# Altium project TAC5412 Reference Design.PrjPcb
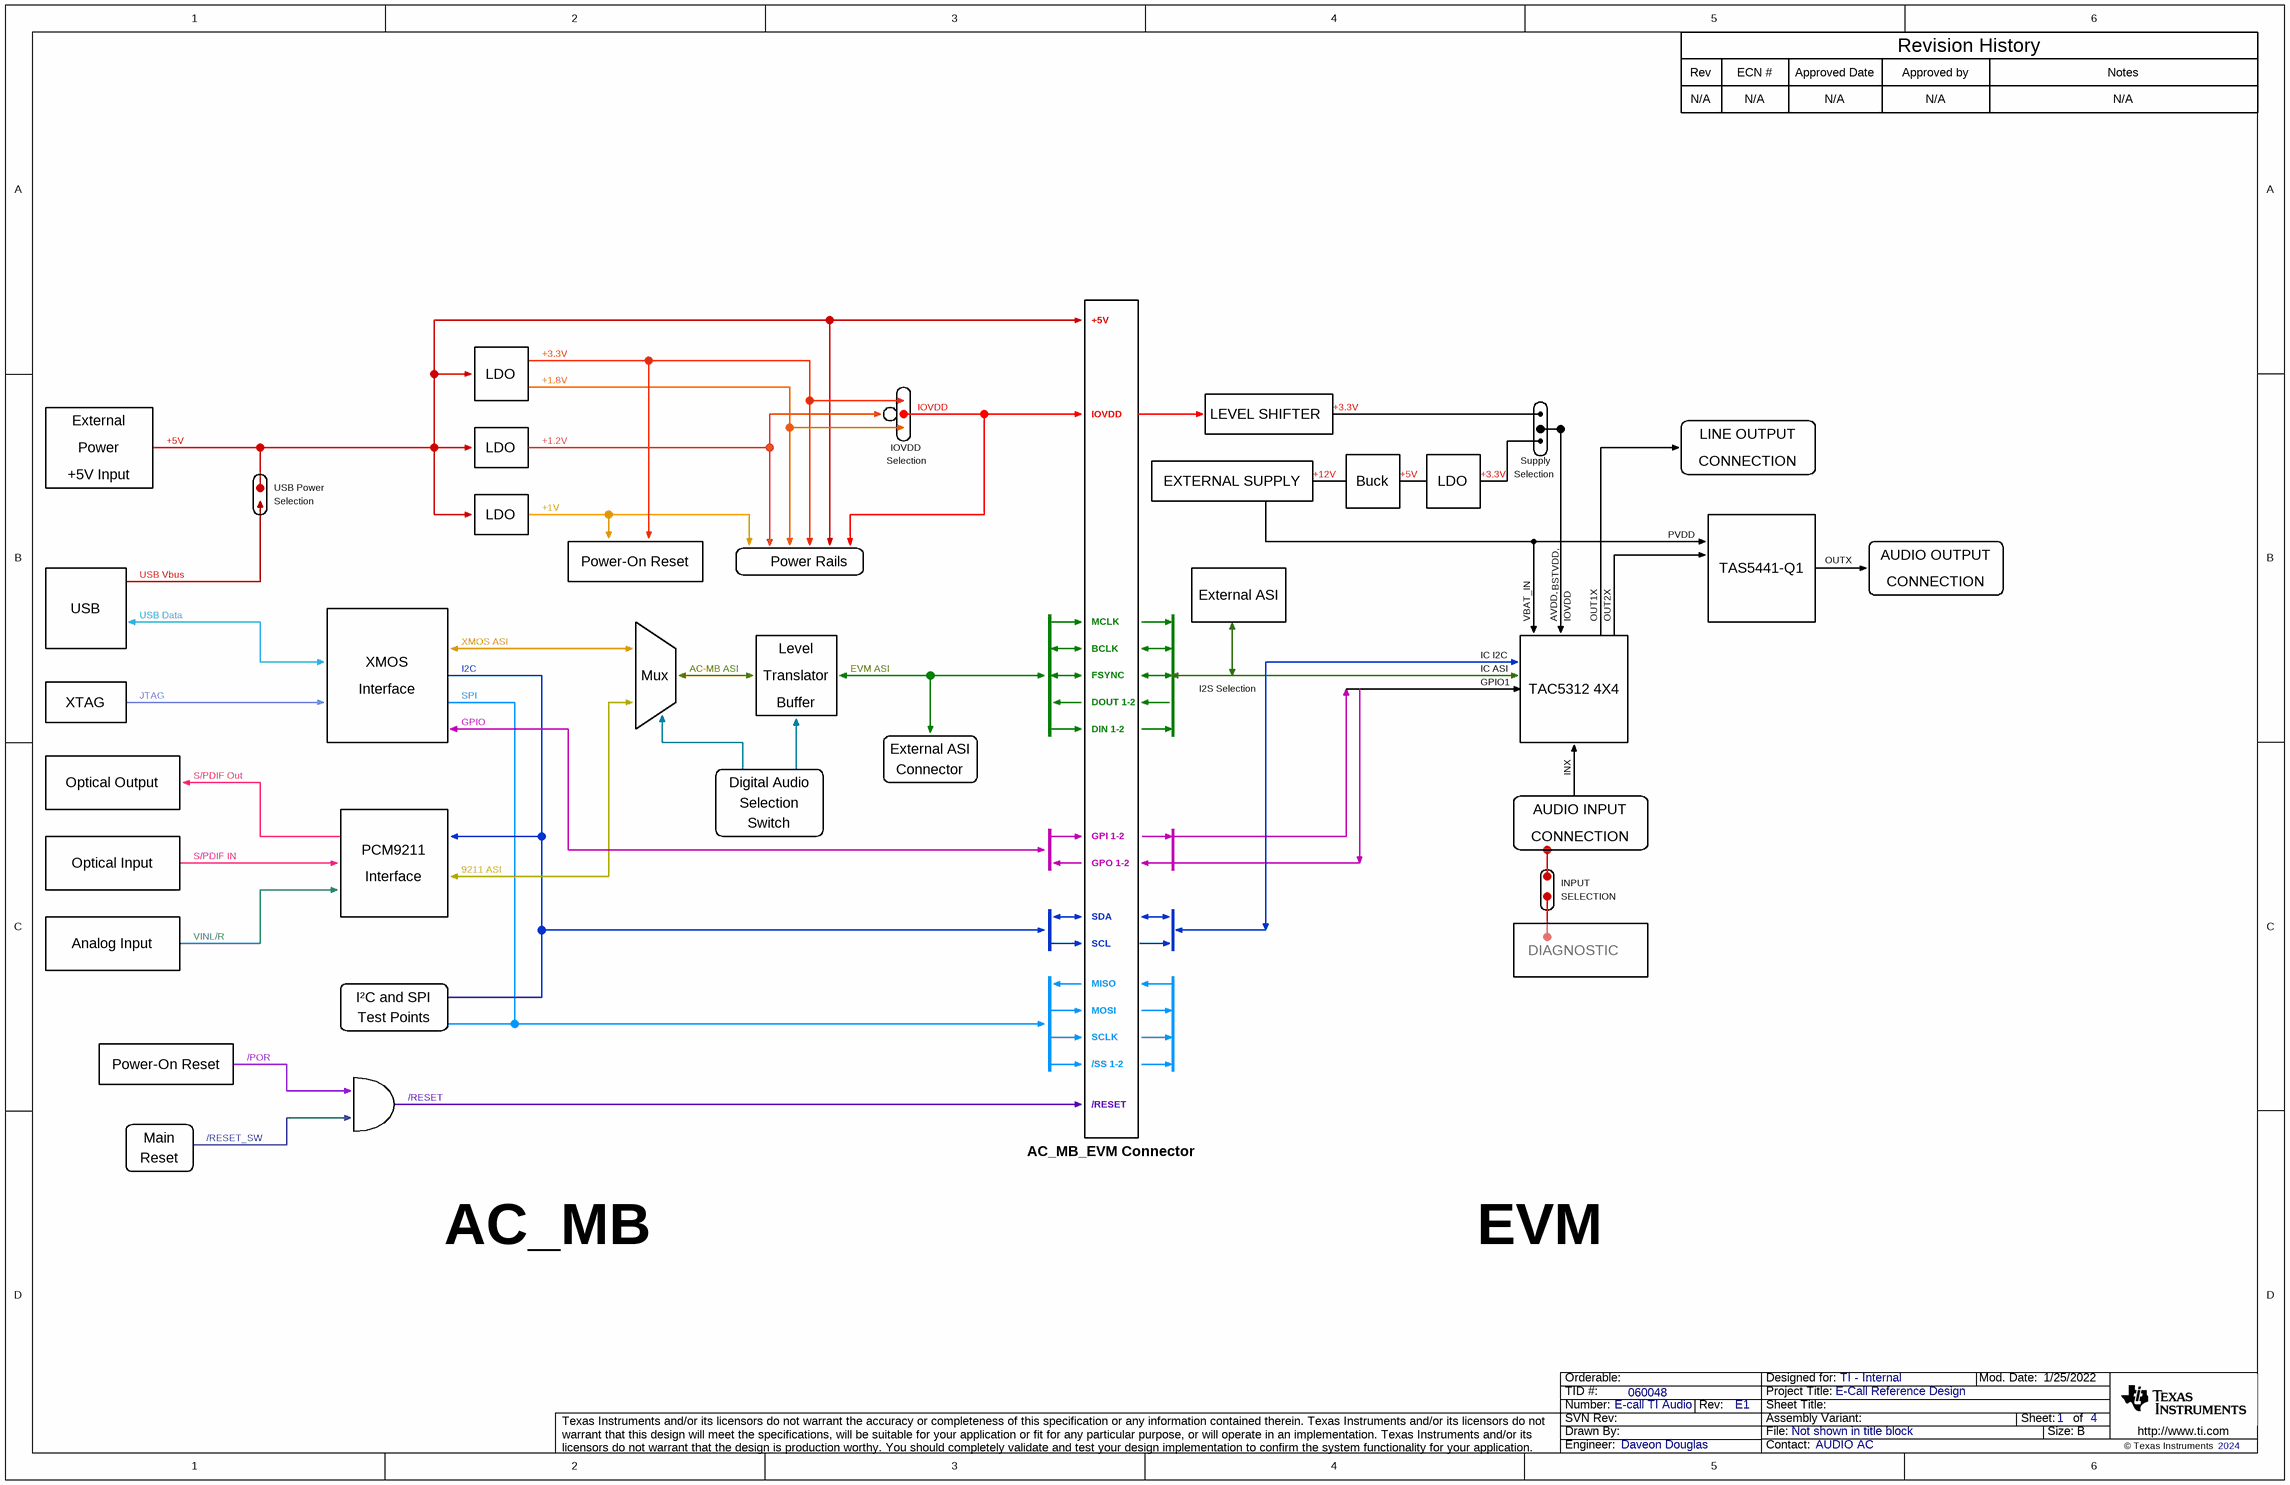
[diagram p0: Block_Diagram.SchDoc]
CopyrightYear: 2024; PCB_Layout: Daveon Douglas; PCB_Rev: Rev A; PRJ_Customer: TI - Internal; PRJ_Engineer: Daveon Douglas; PRJ_Number: E-call TI Audio; PRJ_Title: E-Call Reference Design; SCH_Rev: E1; TechSupport: AUDIO AC; TID: 060048
4 sheets, 139 parts. Net scope: flat (ports and power ports of the same name join across sheets).
Board file: TAC5412 Reference Design.PcbDoc
Sheets:
  Block_Diagram.SchDoc
  Schematic1.SchDoc
  Schematic2.SchDoc
  Hardware.SchDoc

## Sheet Block_Diagram.SchDoc
size 431 x 279 mm; Date: Not shown in title block; ApprovedBy: Not shown in title block; CheckedBy: Not shown in title block; Author: Not shown in title block; CompanyName: Not shown in title block; Engineer: Not shown in title block; Organization: Not shown in title block; Address1: Not shown in title block; Address2: Not shown in title block; Address3: Not shown in title block; Address4: Not shown in title block; DocumentNumber: 1; Revision: Use project parameter SCH_Rev; SheetNumber: 1; SheetTotal: 4; PageSetup: Record=PageOptions¦CenterHorizontal=True¦CenterVertical=True¦PrintScale=1.00¦XCorrection=1.00¦YCorrection=1.00¦PrintKind=0¦BorderSize=5000000¦LeftOffset=0¦BottomOffset=0¦Orientation=2¦PaperLength=1000¦PaperWidth=1000¦Scale=100¦PaperSource=15¦PrintQuality=600¦MediaType=1¦DitherType=10¦PaperKind=Letter¦PrintScaleMode=1

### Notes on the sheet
- Rev
- N/A
- ECN #
- Approved Date
- Approved by
- Revision History
- Notes
- +3.3V
- +5V
- External
- LDO
- +1.8V
- IOVDD
- LEVEL SHIFTER
- LINE OUTPUT
- +5V Input
- Power
- USB Power
- Selection
- +1.2V
- EXTERNAL SUPPLY
- +12V
- Buck
- Supply
- CONNECTION
- +1V
- Power-On Reset
- Power Rails
- PVDD
- TAS5441-Q1
- OUTX
- AUDIO OUTPUT
- USB
- USB Data
- USB Vbus
- MCLK
- External ASI
- VBAT_IN
- BSTVDD,
- AVDD,
- OUT1X
- OUT2X
- XTAG
- JTAG
- XMOS
- Interface
- SPI
- I2C
- XMOS ASI
- Mux
- AC-MB ASI
- Buffer
- Level
- Translator
- EVM ASI
- BCLK
- FSYNC
- DOUT 1-2
- I2S Selection
- IC ASI
- IC I2C
- GPIO1
- TAC5312 4X4
- GPIO
- Connector
- DIN 1-2
- Optical Output
- S/PDIF Out
- Digital Audio
- Switch
- GPI 1-2
- INX
- AUDIO INPUT
- Optical Input
- S/PDIF IN
- PCM9211
- 9211 ASI
- GPO 1-2
- INPUT
- SELECTION
- Analog Input
- VINL/R
- SDA
- SCL
- DIAGNOSTIC
- I²C and SPI
- Test Points
- MISO
- MOSI
- SCLK
- /POR
- /RESET
- /SS 1-2
- Main
- Reset
- /RESET_SW
- AC_MB_EVM Connector
- AC_MB
- EVM

## Sheet Schematic1.SchDoc
size 431 x 279 mm; Date: Not shown in title block; ApprovedBy: Not shown in title block; CheckedBy: Not shown in title block; Author: Not shown in title block; CompanyName: Not shown in title block; Engineer: Not shown in title block; Organization: Not shown in title block; Address1: Not shown in title block; Address2: Not shown in title block; Address3: Not shown in title block; Address4: Not shown in title block; DocumentNumber: 2; Revision: Use project parameter SCH_Rev; SheetNumber: 2; SheetTotal: 4; PageSetup: Record=PageOptions¦CenterHorizontal=True¦CenterVertical=True¦PrintScale=1.00¦XCorrection=1.00¦YCorrection=1.00¦PrintKind=0¦BorderSize=5000000¦LeftOffset=0¦BottomOffset=0¦Orientation=2¦PaperLength=1000¦PaperWidth=1000¦Scale=100¦PaperSource=15¦PrintQuality=600¦MediaType=1¦DitherType=10¦PaperKind=Letter¦PrintScaleMode=1
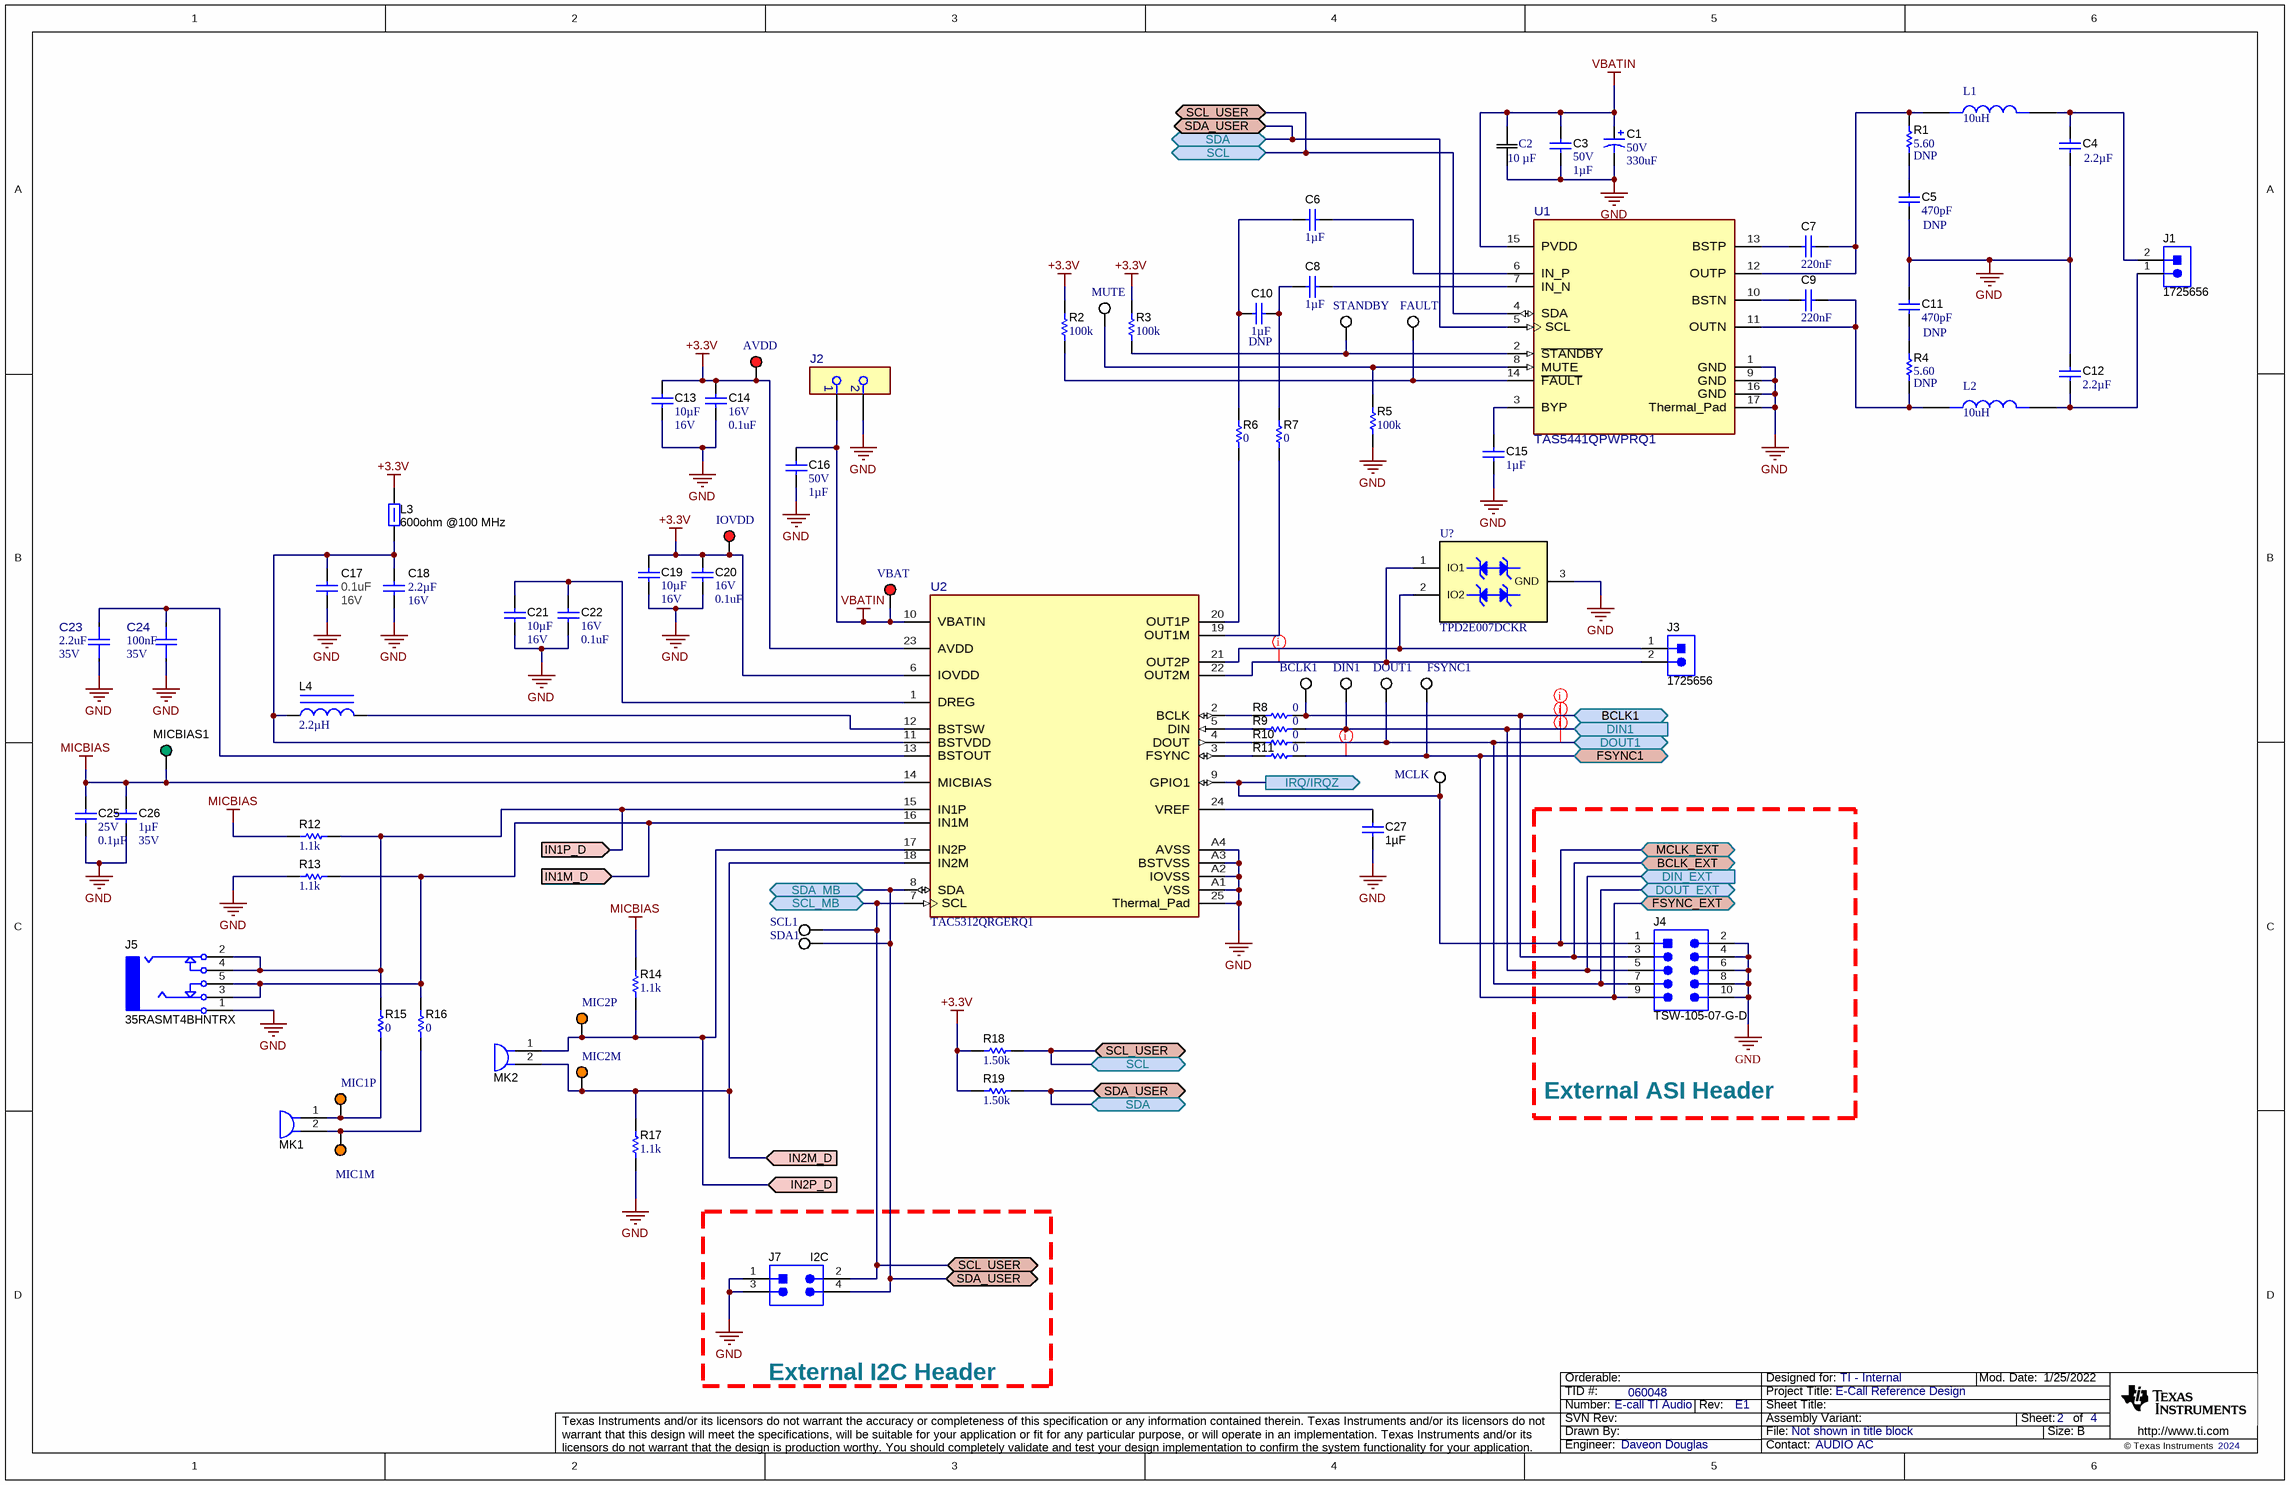
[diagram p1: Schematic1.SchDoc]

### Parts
AVDD  5000  [Keystone5000]  (value not drawn)
BCLK1  5002  [Keystone5002]  (value not drawn)
C1  VDC_V: 50V  ValueDisplayed: 330uF  [Nichicon_1000x1000]  (hidden comment: UCM1H331MNL1GS)
C2  value 10 µF  [CAP_CL32_SAM]  (hidden comment: CL32B106KBJNNNE)
C3  VDC_V: 50V  ValueDisplayed: 1µF  [0805_HV]  (hidden comment: GJ821BR71H105KA12L)
C4  ValueDisplayed: 2.2µF  [0805_HV]  (hidden comment: GCM21BR71E225KA73L)
C5  Cap_F: 470pF  [0603]  (hidden comment: GRM188R72E471KW07D)
C6  Cap_F: 1µF  [0603S]  (hidden comment: CGA3E1X7R1E105K080AC)
C7  Cap_F: 220nF  [0603]  (hidden comment: GCM188R71E224KA55D)
C8  Cap_F: 1µF  [0603S]  (hidden comment: CGA3E1X7R1E105K080AC)
C9  Cap_F: 220nF  [0603]  (hidden comment: GCM188R71E224KA55D)
C10  Cap_F: 1µF  [0603S]  (hidden comment: CGA3E1X7R1E105K080AC)
C11  Cap_F: 470pF  [0603]  (hidden comment: GRM188R72E471KW07D)
C12  ValueDisplayed: 2.2µF  [0805_HV]  (hidden comment: GCM21BR71E225KA73L)
C13  Cap_F: 10µF  VDC_V: 16V  [0805_HV]  (hidden comment: CL21B106KOQNNNG)
C14  VDC_V: 16V  ValueDisplayed: 0.1uF  [0402]  (hidden comment: 885012205037)
C15  Cap_F: 1µF  [0603S]  (hidden comment: CGA3E1X7R1E105K080AC)
C16  VDC_V: 50V  ValueDisplayed: 1µF  [0805_HV]  (hidden comment: GJ821BR71H105KA12L)
C17  VDC_V: 16V  ValueDisplayed: 0.1uF  [0402L]  (hidden comment: 885012205037)
C18  Cap_F: 2.2µF  VDC_V: 16V  [0805_HV]  (hidden comment: C2012X7R1C225K125AB)
C19  Cap_F: 10µF  VDC_V: 16V  [0805_HV]  (hidden comment: CL21B106KOQNNNG)
C20  VDC_V: 16V  ValueDisplayed: 0.1uF  [0402]  (hidden comment: 885012205037)
C21  Cap_F: 10µF  VDC_V: 16V  [0805_HV]  (hidden comment: CL21B106KOQNNNG)
C22  VDC_V: 16V  ValueDisplayed: 0.1uF  [0402]  (hidden comment: 885012205037)
C23  VDC_V: 35V  ValueDisplayed: 2.2uF  [FP-C3216X7R1V225K160AE_1206-MFG]  (hidden comment: C3216X7R1V225K160AE)
C24  ValueDisplayed: 100nF  VDC_V: 35V  [FP-CGA2B3X7R1V104K050BB_0402-MFG]  (hidden comment: CGA2B3X7R1V104K050BB)
C25  VDC_V: 25V  ValueDisplayed: 0.1µF  [0402]  (hidden comment: CGA2B3X7R1E104K050BB)
C26  Cap_F: 1µF  VDC_V: 35V  [0603]  (hidden comment: C1608X7R1V105K080AC)
C27  Cap_F: 1µF  [0603]  (hidden comment: 885012206052)
DIN1  5002  [Keystone5002]  (value not drawn)
DOUT1  5002  [Keystone5002]  (value not drawn)
FAULT  5002  [Keystone5002]  (value not drawn)
FSYNC1  5002  [Keystone5002]  (value not drawn)
IOVDD  5000  [Keystone5000]  (value not drawn)
J1  1725656  [CONN_1725656]
J2  691137710002  [FP-691137710002_HDR2-MFG]  (value not drawn)
J3  1725656  [CONN_1725656]
J4  TSW-105-07-G-D  [TSW-105-07-G-D]
J5  35RASMT4BHNTRX  [Switchcraft_35RASM]
J7  I2C  [Sullins_PxC02DAAN]
L1  value 10uH  [IND_VLS6045EX-100M-H]  (hidden comment: VLS6045EX-100M-H)
L2  value 10uH  [IND_VLS6045EX-100M-H]  (hidden comment: VLS6045EX-100M-H)
L3  600ohm @100 MHz  [0603]
L4  ValueDisplayed: 2.2µH  [0806]  (hidden comment: LPWI201610H2R2T)
MCLK  5002  [Keystone5002]  (value not drawn)
MIC1M  5003  [Keystone5003]  (value not drawn)
MIC1P  5003  [Keystone5003]  (value not drawn)
MIC2M  5003  [Keystone5003]  (value not drawn)
MIC2P  5003  [Keystone5003]  (value not drawn)
MICBIAS1  MBIAS  [Keystone_5116]  (value not drawn)
MK1  POM-2242P-C33-R  [MIC_POM-2242P-C33-R]  (value not drawn)
MK2  POM-2242P-C33-R  [MIC_POM-2242P-C33-R]  (value not drawn)
MUTE  5002  [Keystone5002]  (value not drawn)
R1  ValueDisplayed: 5.60  [0805_HV]  (hidden comment: RL1220S-5R6-F)
R2  ValueDisplayed: 100k  [0603]  (hidden comment: CPF0603B100KE)
R3  ValueDisplayed: 100k  [0603]  (hidden comment: CPF0603B100KE)
R4  ValueDisplayed: 5.60  [0805_HV]  (hidden comment: RL1220S-5R6-F)
R5  ValueDisplayed: 100k  [0603]  (hidden comment: CPF0603B100KE)
R6  ValueDisplayed: 0  [0603]  (hidden comment: RC0603JR-070RL)
R7  ValueDisplayed: 0  [0603]  (hidden comment: RC0603JR-070RL)
R8  ValueDisplayed: 0  [0603]  (hidden comment: PMR03EZPJ000)
R9  ValueDisplayed: 0  [0603]  (hidden comment: PMR03EZPJ000)
R10  ValueDisplayed: 0  [0603]  (hidden comment: PMR03EZPJ000)
R11  ValueDisplayed: 0  [0603]  (hidden comment: PMR03EZPJ000)
R12  ValueDisplayed: 1.1k  [0603]  (hidden comment: CRCW06031K10JNEA)
R13  ValueDisplayed: 1.1k  [0603]  (hidden comment: CRCW06031K10JNEA)
R14  ValueDisplayed: 1.1k  [0603]  (hidden comment: CRCW06031K10JNEA)
R15  ValueDisplayed: 0  [0603]  (hidden comment: RC0603JR-070RL)
R16  ValueDisplayed: 0  [0603]  (hidden comment: RC0603JR-070RL)
R17  ValueDisplayed: 1.1k  [0603]  (hidden comment: CRCW06031K10JNEA)
R18  ValueDisplayed: 1.50k  [0603]  (hidden comment: RC0603FR-071K5L)
R19  ValueDisplayed: 1.50k  [0603]  (hidden comment: RC0603FR-071K5L)
SCL1  5002  [Keystone5002]  (value not drawn)
SDA1  5002  [Keystone5002]  (value not drawn)
STANDBY  5002  [Keystone5002]  (value not drawn)
U1  TAS5441QPWPRQ1  [PWP0016B-MFG]
U2  TAC5312QRGERQ1  [RGE0024W-MFG]
U?  TPD2E007DCKR  [DCK0003A_L]
VBAT  5000  [Keystone5000]  (value not drawn)

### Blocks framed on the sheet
External ASI Header: J4
External I2C Header: J7

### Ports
BCLK1 (bidir), BCLK_EXT (bidir), DIN1 (in), DIN_EXT (in), DOUT1 (bidir), DOUT_EXT (bidir), FSYNC1 (bidir), FSYNC_EXT (bidir), IN1M_D (in), IN1P_D (in), IN2M_D (in), IN2P_D (in), IRQ/IRQZ (out), MCLK_EXT (bidir), SCL (bidir), SCL_MB (bidir), SCL_USER (bidir), SDA (bidir), SDA_MB (bidir), SDA_USER (bidir)

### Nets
+3.3V: AVDD.1 C13.1 C14.1 C19.1 C20.1 IOVDD.1 L3.2 R2.1 R3.1 R18.1 R19.1 U2.6(IOVDD) U2.23(AVDD)
GND: C1.2(-) C2.1 C3.2 C4.2 C5.2 C11.1 C12.1 C13.2 C14.2 C15.2 C16.2 C17.2 C18.2 C19.2 C20.2 C21.2 C22.2 C23.1 C24.1 C25.2 C26.2 C27.2 J2.2 J4.2 J4.4 J4.6 J4.8 J4.10 J5.1(SLEEVE) J7.1 J7.3 R5.1 R13.2 R17.2 U1.1(GND) U1.9(GND) U1.16(GND) U1.17(Thermal_Pad) U2.25(Thermal_Pad) U2.A1(VSS) U2.A2(IOVSS) U2.A3(BSTVSS) U2.A4(AVSS) U?.3(GND)
MICBIAS: C25.1 C26.1 MICBIAS1.1 R12.2 R14.1 U2.14(MICBIAS)
VBATIN: C1.1(+) C2.2 C3.1 C16.1 J2.1 U1.15(PVDD) U2.10(VBATIN) VBAT.1
BCLK1: BCLK1.1 J4.3 R8.2 ; port BCLK1, port BCLK_EXT
DIN1: DIN1.1 J4.5 R9.2 ; port DIN1, port DIN_EXT
DOUT1: DOUT1.1 J4.7 R10.2 ; port DOUT1, port DOUT_EXT
FSYNC1: FSYNC1.1 J4.9 R11.2 ; port FSYNC1, port FSYNC_EXT
IN1M_D: J5.3(TIP) J5.5(TIP_SWITCH) R13.1 R16.2 U2.16(IN1M) ; port IN1M_D
IN1P_D: J5.2(RING) J5.4(RING_SWITCH) R12.1 R15.2 U2.15(IN1P) ; port IN1P_D
IN2M_D: MIC2M.1 MK2.2 R17.1 U2.18(IN2M) ; port IN2M_D
IN2P_D: MIC2P.1 MK2.1 R14.2 U2.17(IN2P) ; port IN2P_D
IRQ/IRQZ: J4.1 MCLK.1 U2.9(GPIO1) ; port IRQ/IRQZ, port MCLK_EXT
SCL: J7.2 R18.2 SCL1.1 U1.4(SDA) U2.7(SCL) ; port SCL_MB, port SCL, port SCL_USER
SDA: J7.4 R19.2 SDA1.1 U1.5(SCL) U2.8(SDA) ; port SDA_MB, port SDA, port SDA_USER
NetC4_1: C4.1 J1.2 L1.2
NetC5_1: C5.1 R1.1
NetC6_1: C6.1 U1.6(IN_P)
NetC6_2: C6.2 C10.2 R6.2
NetC7_1: C7.1 L1.1 R1.2 U1.12(OUTP)
NetC7_2: C7.2 U1.13(BSTP)
NetC8_1: C8.1 U1.7(IN_N)
NetC8_2: C8.2 C10.1 R7.2
NetC9_1: C9.1 L2.1 R4.1 U1.11(OUTN)
NetC9_2: C9.2 U1.10(BSTN)
NetC11_2: C11.2 R4.2
NetC12_2: C12.2 J1.1 L2.2
NetC15_1: C15.1 U1.3(BYP)
NetC17_1: C17.1 C18.1 L3.1 L4.1 U2.11(BSTVDD)
NetC21_1: C21.1 C22.1 U2.1(DREG)
NetC23_2: C23.2 C24.2 U2.13(BSTOUT)
NetC27_1: C27.1 U2.24(VREF)
NetFAULT_1: FAULT.1 R2.2 U1.14(~{FAULT})
NetJ3_1: J3.1 U2.21(OUT2P) U?.2(IO2)
NetJ3_2: J3.2 U2.22(OUT2M) U?.1(IO1)
NetL4_2: L4.2 U2.12(BSTSW)
NetMIC1M_1: MIC1M.1 MK1.2 R16.1
NetMIC1P_1: MIC1P.1 MK1.1 R15.1
NetMUTE_1: MUTE.1 R5.2 U1.8(MUTE)
NetR3_2: R3.2 STANDBY.1 U1.2(~{STANDBY})
NetR6_1: R6.1 U2.20(OUT1P)
NetR7_1: R7.1 U2.19(OUT1M)
NetR8_1: R8.1 U2.2(BCLK)
NetR9_1: R9.1 U2.5(DIN)
NetR10_1: R10.1 U2.4(DOUT)
NetR11_1: R11.1 U2.3(FSYNC)

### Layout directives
net class 16 Ohm: NetJ3_2
net class ASI: BCLK1, DIN1, DOUT1, FSYNC1

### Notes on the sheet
- (near R1) DNP
- (near C5) DNP
- (near C10) DNP
- DNP
- (near R4) DNP

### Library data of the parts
AVDD IOVDD VBAT = CMP-0055137-2: Test Point, Miniature, Red, TH; Manufacturer: Keystone Electronics; CNHeader: FALSE; Green_Lifecycle: Active; Green_REACh: Passed; ContactFinish: Silver; CT: TRUE
BCLK1 DIN1 DOUT1 FAULT FSYNC1 MCLK MUTE SCL1 SDA1 STANDBY = CMP-0055139-2: Test Point, Miniature, White, TH; Manufacturer: Keystone Electronics; CNHeader: FALSE; Green_Lifecycle: Active; Green_REACh: Passed; ContactFinish: Silver; CT: TRUE
C1 = CMP-0064900-1: CAP, AL, 330 uF, 50 V, +/- 20%, SMD; Manufacturer: Nichicon; TaMin_C: -55°C; Polarized: Y; SizeAreaWB_mm2: 151.29; Value1: Unknown; U/M: EA; Value: 330uF; TaMax_C: 105°C; SizeZ_mm: 10.8; SizeX_mm: 10.3; Cap_Case: 10x10mm; SizeArea_mm2: 106.09; CompType: Capacitor; AEC Qualified: N; Cap_F: 330µF; IRMS_A: 900mA; AEC Category: Q200
C2 = CL32B106KBJNNNE: 10 µF ±10% 50V Ceramic Capacitor X7R 1210 (3225 Metric); Mfr_Name: Samsung; Manufacturer: Samsung Electro-Mechanics
C3 C16 = CMP-0750127-1: CAP, CERM, 1 µF, 50 V,+/- 10%, X7R, 0805; Manufacturer: MuRata; TaMin_C: -55°C; Polarized: N; SizeAreaWB_mm2: 6.75; U/M: EA; Value: 1uF; TaMax_C: 125°C; SizeZ_mm: 1.45; SizeX_mm: 2; SizeY_mm: 1.25; Cap_Case: 0805; SizeArea_mm2: 2.5; AEC Category: Q200
C4 C12 = CMP-0083622-1: CAP, CERM, 2.2 µF, 25 V,+/- 10%, X7R, AEC-Q200 Grade 1, 0805; Manufacturer: MuRata; TaMin_C: -55°C; Polarized: N; SizeAreaWB_mm2: 6.75; U/M: EA; Value: 2.2uF; TaMax_C: 125°C; SizeZ_mm: 1.45; SizeX_mm: 2; SizeY_mm: 1.25; Cap_Case: 0805; Value2: 25V; SizeArea_mm2: 2.5; AEC Qualified: Y; AEC Grade: 1; AEC Category: Q200
C5 C11 = CMP-0007495-4: CAP, CERM, 470 pF, 250 V, +/- 10%, X7R, 0603; Manufacturer: MuRata; TaMin_C: -55°C; Polarized: N; SizeAreaWB_mm2: 4.68; Value1: Unknown; U/M: EA; Value: 470pF; TaMax_C: 125°C; SizeZ_mm: 1; SizeX_mm: 1.6; SizeY_mm: 0.8; Value2: 250V; SizeArea_mm2: 1.28; AEC Category: Q200
C6 C8 C10 C15 = CMP-0076705-3: CAP, CERM, 1 µF, 25 V,+/- 10%, X7R, AEC-Q200 Grade 1, 0603; Manufacturer: TDK; SizeAreaWB_mm2: 4.68; SizeArea_mm2: 1.28; AEC Qualified: Y; AEC Category: Q200; Value: 1uF; TaMax_C: 125°C; SizeZ_mm: 1.0; AEC Grade: 1; Polarized: N; TaMin_C: -55°C; VDC_V: 25V; SizeY_mm: 0.8; U/M: EA; SizeX_mm: 1.6; Cap_Case: 1.6x0.8x0.8mm
C7 C9 = CMP-0007140-4: CAP, CERM, 0.22 uF, 25 V, +/- 10%, X7R, AEC-Q200 Grade 1, 0603; Manufacturer: MuRata; TaMin_C: -55°C; Polarized: N; SizeAreaWB_mm2: 4.68; Value1: Unknown; U/M: EA; Value: 0.22uF; TaMax_C: 125°C; SizeZ_mm: 1; SizeX_mm: 1.6; SizeY_mm: 0.8; Value2: 25V; SizeArea_mm2: 1.28; AEC Qualified: Y; AEC Category: Q200
C13 C19 C21 = CMP-0860967-1: CAP, CERM, 10 µF, 16 V,+/- 10%, X7R, 0805; Manufacturer: Samsung; TaMin_C: -55°C; AEC Qualified: N; U/M: EA; TaMax_C: 125°C; SizeAreaWB_mm2: 6.75; SizeZ_mm: 1.45; Value: 10uF; SizeY_mm: 1.25; SizeArea_mm2: 2.5; AEC Category: Q200; SizeX_mm: 2; Cap_Case: 0805
C14 C20 C22 = CMP-0006228-2: CAP, CERM, 0.1 uF, 16 V, +/- 10%, X7R, 0402; Manufacturer: Wurth Elektronik; TaMin_C: -55°C; Polarized: N; SizeAreaWB_mm2: 3; Value1: Unknown; U/M: EA; Value: 0.1uF; TaMax_C: 125°C; SizeZ_mm: 0.6; SizeX_mm: 1; SizeY_mm: 0.5; Cap_F: 100nF; AEC Category: Q200
C17 = CMP-0006228-2: CAP, CERM, 0.1 uF, 16 V, +/- 10%, X7R, 0402; Manufacturer: Wurth Elektronik; TaMin_C: -55°C; Polarized: N; SizeAreaWB_mm2: 3; Value1: Unknown; U/M: EA; Value: 0.1uF; TaMax_C: 125°C; SizeZ_mm: 0.6; SizeX_mm: 1; SizeY_mm: 0.5; Cap_Case: 0402; CompType: Capacitor; Cap_F: 100nF; AEC Category: Q200
C18 = CMP-0007867-2: CAP, CERM, 2.2 uF, 16 V, +/- 10%, X7R, 0805; Manufacturer: TDK; TaMin_C: -55°C; ESR_ohm: 4.9m; Polarized: N; SizeAreaWB_mm2: 6.75; Value1: 0.0049 ohm; U/M: EA; Value: 2.2uF; TaMax_C: 125°C; SizeZ_mm: 1.45; SizeX_mm: 2; SizeY_mm: 1.25; Cap_Case: 0805; SizeArea_mm2: 2.5; AEC Category: Q200
C23 = CMP-0096782-1: Capacitor Ceramic 2.2uF 35V X7R 10% 1206 T/R; Manufacturer: TDK; AEC Qualified: No; Value: 2.2µF; SizeZ_mm: 1.9mm; TempCo: 15%
C24 = CMP-0094936-1: Cap Ceramic 100nF 35V X7R 10% Pad SMD 0402 +125°C Automotive T/R; Manufacturer: TDK Corporation; SizeZ_mm: 0.55mm; AEC Qualified: Yes; Tolerance_%: 0.1%; AEC Grade: Grade 1; TempCo: 15%
C25 = CMP-0080610-1: CAP, CERM, 0.1 µF, 25 V,+/- 10%, X7R, AEC-Q200 Grade 1, 0402; Manufacturer: TDK; TaMin_C: -55°C; Polarized: N; SizeAreaWB_mm2: 3; U/M: EA; Value: 0.1uF; TaMax_C: 125°C; SizeZ_mm: 0.6; SizeX_mm: 1; SizeY_mm: 0.5; AEC Qualified: Y; Cap_F: 100nF; AEC Category: Q200
C26 = CMP-0007052-4: CAP, CERM, 1 uF, 35 V, +/- 10%, X7R, 0603; Manufacturer: TDK; TaMin_C: -55°C; Polarized: N; SizeAreaWB_mm2: 4.68; Value1: Unknown; U/M: EA; Value: 1uF; TaMax_C: 125°C; SizeZ_mm: 1; SizeX_mm: 1.6; SizeY_mm: 0.8; SizeArea_mm2: 1.28; AEC Category: Q200
C27 = CMP-0006831-4: CAP, CERM, 1 uF, 16 V, +/- 10%, X7R, 0603; Manufacturer: Wurth Elektronik; TaMin_C: -55°C; Polarized: N; SizeAreaWB_mm2: 4.68; Value1: Unknown; U/M: EA; Value: 1uF; TaMax_C: 125°C; SizeZ_mm: 1; SizeX_mm: 1.6; SizeY_mm: 0.8; Value2: 16V; SizeArea_mm2: 1.28; AEC Category: Q200
J1 J3 = CMP-0055479-2: Terminal Block, 100mil, 2x1, 6A, 63V, TH; Manufacturer: Phoenix Contact; Green_REACh: Incomplete; CNHeader: FALSE; CT: TRUE; Green_Lifecycle: Not Set
J2 = CMP-0087503-1: TERM BLK 2POS SIDE ENTRY 5MM PCB; Manufacturer: Würth Elektronik; Symbol Name: SYM-691137710002; Row_Count: 1; Current_A: 16A; ContactFinish: Tin,Nickel; Voltage_V: 300V
J4 = CMP-0075410-2: Header, 100mil, 5x2, Gold, TH; Manufacturer: Samtec; Pitch_mm: 2.54; Cert_VDE: N; Gender: Male; Cert_CSA: Y; Voltage_V: 550V; Green_REACh: Passed; Current_A: 6.3A; Green_Lifecycle: Active; Row_Count: 2
J5 = CMP-0074987-1: Audio Jack, 3.5mm, Stereo, R/A, SMT; Manufacturer: Switchcraft; CT: True; CompType: Audio Connector; CNHeader: False
J7 = CMP-0054598-1: Header, 2.54mm, 2x2, Gold, TH; Manufacturer: Sullins Connector Solutions; PartNumber: PBC02DAAN; CNHeader: TRUE; Current_A: 3A; Shrouded: N; Gender: Male; Voltage_V: 1.8kV; Row_Count: 2; RowSpacing_mm: 2.54; CT: FALSE; Cert_UL: Y
L1 L2 = VLS6045EX-100M-H: Inductor Power Shielded Wirewound 10uH 20% 100KHz Ferrite 3.4A 0.0611Ohm DCR Automotive T/R; MF: TDK Corporation
L3 = CMP-0003285-2: Ferrite Bead, 600 ohm @ 100 MHz, 1 A, 0603; Manufacturer: Wurth Elektronik; PartNumber: 782633601; Ztyp@1GHz_Ohm: 228.849; ZTyp@100MHz_Ohm: 600; SizeAreaWB_mm2: 4.68; DCR_ohm: 0.2; Value1: 0.2 ohm; Imax_A: 1A; SizeZ_mm: 1; SizeX_mm: 1.6; SizeY_mm: 0.8; SizeArea_mm2: 1.28
L4 = CMP-0083752-1: Inductor, Shielded, Metal Composite, 2.2 µH, 2.2 A, 0.1 ohm, SMD; Manufacturer: Littelfuse; SizeAreaWB_mm2: 7.8; Irms: 2.2A @ 40C rise; SizeArea_mm2: 3.2; AEC Qualified: N; AEC Category: Q200; Value: 2.2uH; SizeZ_mm: 1; Imax_A: 2.2A; SizeY_mm: 1.6; Isat: 2.5A @ 30% inductance drop; Value1: 0.1 ohm; DCR_ohm: 0.1; SizeX_mm: 2
MIC1M MIC1P MIC2M MIC2P = CMP-0055140-2: Test Point, Miniature, Orange, TH; Manufacturer: Keystone Electronics; CNHeader: FALSE; Green_Lifecycle: Active; Green_REACh: Passed; ContactFinish: Silver; CT: TRUE
MICBIAS1 = CMP-0055164-1: Test Point, Miniature, Green, TH; Manufacturer: Keystone; PartNumber: 5116; CNHeader: FALSE; Green_Lifecycle: Active; Green_REACh: Passed; Row_Count: 1; ContactFinish: Silver; CT: TRUE; Cert_UL: Y
MK1 MK2 = CMP-0001912-2: Microphone, Condenser, Analog, Omnidirectional, -42DB, TH; Manufacturer: PUI Audio
R1 R4 = CMP-0021974-2: RES, 5.60, 1%, 0.33 W, 0805; Manufacturer: Susumu Co Ltd; Power_W: 330mW; TempCo: 200 ppm/C; Value_Code: 5R60; U/M: EA; Value: 5.60; Res_ohm: 5.6; SizeX_mm: 2; SizeY_mm: 1.25; SizeZ_mm: 1.45; Value2: 0.33W; SizeArea_mm2: 2.5; AEC Category: Q200
R2 R3 R5 = CMP-0023346-3: RES, 100 k, 0.1%, 0.063 W, 0603; Manufacturer: TE Connectivity; Power_W: 63mW; TempCo: 25 ppm/C; U/M: EA; Value: 100k; EIA_Code: E192; SizeX_mm: 1.6; SizeY_mm: 0.8; SizeZ_mm: 1; Value2: 0.063W; SizeArea_mm2: 1.28; VDC_V: 50V; AEC Category: Q200
R6 R7 R15 R16 = CMP-0025885-5: RES, 0, 5%, 0.1 W, 0603; Manufacturer: Yageo; Power_W: 100mW; TempCo: 200 ppm/C; Value_Code: 0000; Value: 0; EIA_Code: E24; SizeX_mm: 1.6; SizeZ_mm: 1; Value2: 0.1W; SizeArea_mm2: 1.28; AEC Qualified: N; VDC_V: 75V; AEC Category: Q200; SizeY_mm: 0.8; SizeAreaWB_mm2: 4.68
R8-R11 = CMP-0086358-1: RES, 0, 0%, 0.25 W, AEC-Q200 Grade 0, 0603; Manufacturer: Rohm; Power_W: 250mW; SizeZ_mm: 1; SizeArea_mm2: 1.28; Value2: 0.25W; SizeAreaWB_mm2: 4.68; Value_Code: 0000; Value: 0; AEC Qualified: Y; AEC Category: Q200; SizeX_mm: 1.6; SizeY_mm: 0.8
R12-R14 R17 = CMP-0025730-4: RES, 1.1 k, 5%, 0.1 W, AEC-Q200 Grade 0, 0603; Manufacturer: Vishay-Dale; Power_W: 100mW; TempCo: 200 ppm/C; Value_Code: 1k10; Value: 1.1k; EIA_Code: E24; SizeX_mm: 1.6; SizeY_mm: 0.8; SizeZ_mm: 1; Value2: 0.1W; SizeArea_mm2: 1.28; AEC Qualified: Y; VDC_V: 75V; AEC Category: Q200; AEC Grade: 0
R18 R19 = CMP-0022883-5: RES, 1.50 k, 1%, 0.1 W, 0603; Manufacturer: Yageo; Power_W: 100mW; TempCo: 100 ppm/C; Value_Code: 1k50; Value: 1.50k; EIA_Code: E96; Res_ohm: 1.5k; SizeX_mm: 1.6; SizeY_mm: 0.8; SizeZ_mm: 1; Value2: 0.1W; SizeArea_mm2: 1.28; AEC Qualified: N; VDC_V: 75V; AEC Category: Q200; SizeAreaWB_mm2: 4.68
U1 = CMP-0088358-2: 22-W Mono Automotive Digital-audio Amplifier with Load Dump and I2C Diagnostics; Manufacturer: Texas Instruments; TaMax_C: +125°C; TaMin_C: -40°C; Power At Speaker R: 22W @ 4Ω; Max Supply Voltage: 18V; CompType: IC; TJmax_C: +155°C; AEC Grade: Grade 1; Number Of Channels: 1; Output Current Per Channel: 3.5A; AEC Category: Q200; SizeZ_mm: 1.2mm; Voltage Gain: 20dB; AEC Qualified: Yes; Standoff Height: 0.05mm; Nominal Supply Current: 16mA; Min Supply Voltage: 4.5V
U2 = CMP-0121019-1: Automotive Low Power Stereo Audio Codec with integrated programmable boost, micbias and diagnostics; Manufacturer: Texas Instruments; SizeZ_mm: 1mm; AEC Qualified: Yes; AEC Grade: Grade 1; Interface: I2C,SPI,I2S; Max Supply Voltage: 3.6V; Min Supply Voltage: 1.08V; Number Of A/D Converters: 2; Resolution: 32bits; Sampling Rate: 8-768ksps; Standoff Height: 0mm; TaMax_C: +125°C; TaMin_C: -40°C; TJmax_C: +150°C
U? = CMP-0043100-2: ESD Protection Array for AC Signal Data Interface, 2 Channels, -40 to +85 degC, 3-pin SC70 (DCK), Green (RoHS & no Sb/Br); Manufacturer: Texas Instruments; IO Leakage Current(nA): 50; IEC 61000-4-2 Contact(+/- kV): 8; IO Capacitance(Typ)(pF): 15; Breakdown Voltage(Min)(V): +/-14; SubFamily: ESD Solution; AEC Category: Q200; AEC Qualified: N; CompType: IC; SizeAreaWB_mm2: 9.3; SizeArea_mm2: 4.2; SizeX_mm: 2.1; SizeY_mm: 2; SizeZ_mm: 1.1

## Sheet Schematic2.SchDoc
size 431 x 279 mm; Date: Not shown in title block; ApprovedBy: Not shown in title block; CheckedBy: Not shown in title block; Author: Not shown in title block; CompanyName: Not shown in title block; Engineer: Not shown in title block; Organization: Not shown in title block; Address1: Not shown in title block; Address2: Not shown in title block; Address3: Not shown in title block; Address4: Not shown in title block; DocumentNumber: 1; Revision: Use project parameter SCH_Rev; SheetNumber: 3; SheetTotal: 4; PageSetup: Record=PageOptions¦CenterHorizontal=True¦CenterVertical=True¦PrintScale=1.00¦XCorrection=1.00¦YCorrection=1.00¦PrintKind=0¦BorderSize=5000000¦LeftOffset=0¦BottomOffset=0¦Orientation=2¦PaperLength=1000¦PaperWidth=1000¦Scale=100¦PaperSource=15¦PrintQuality=600¦MediaType=1¦DitherType=10¦PaperKind=Letter¦PrintScaleMode=1
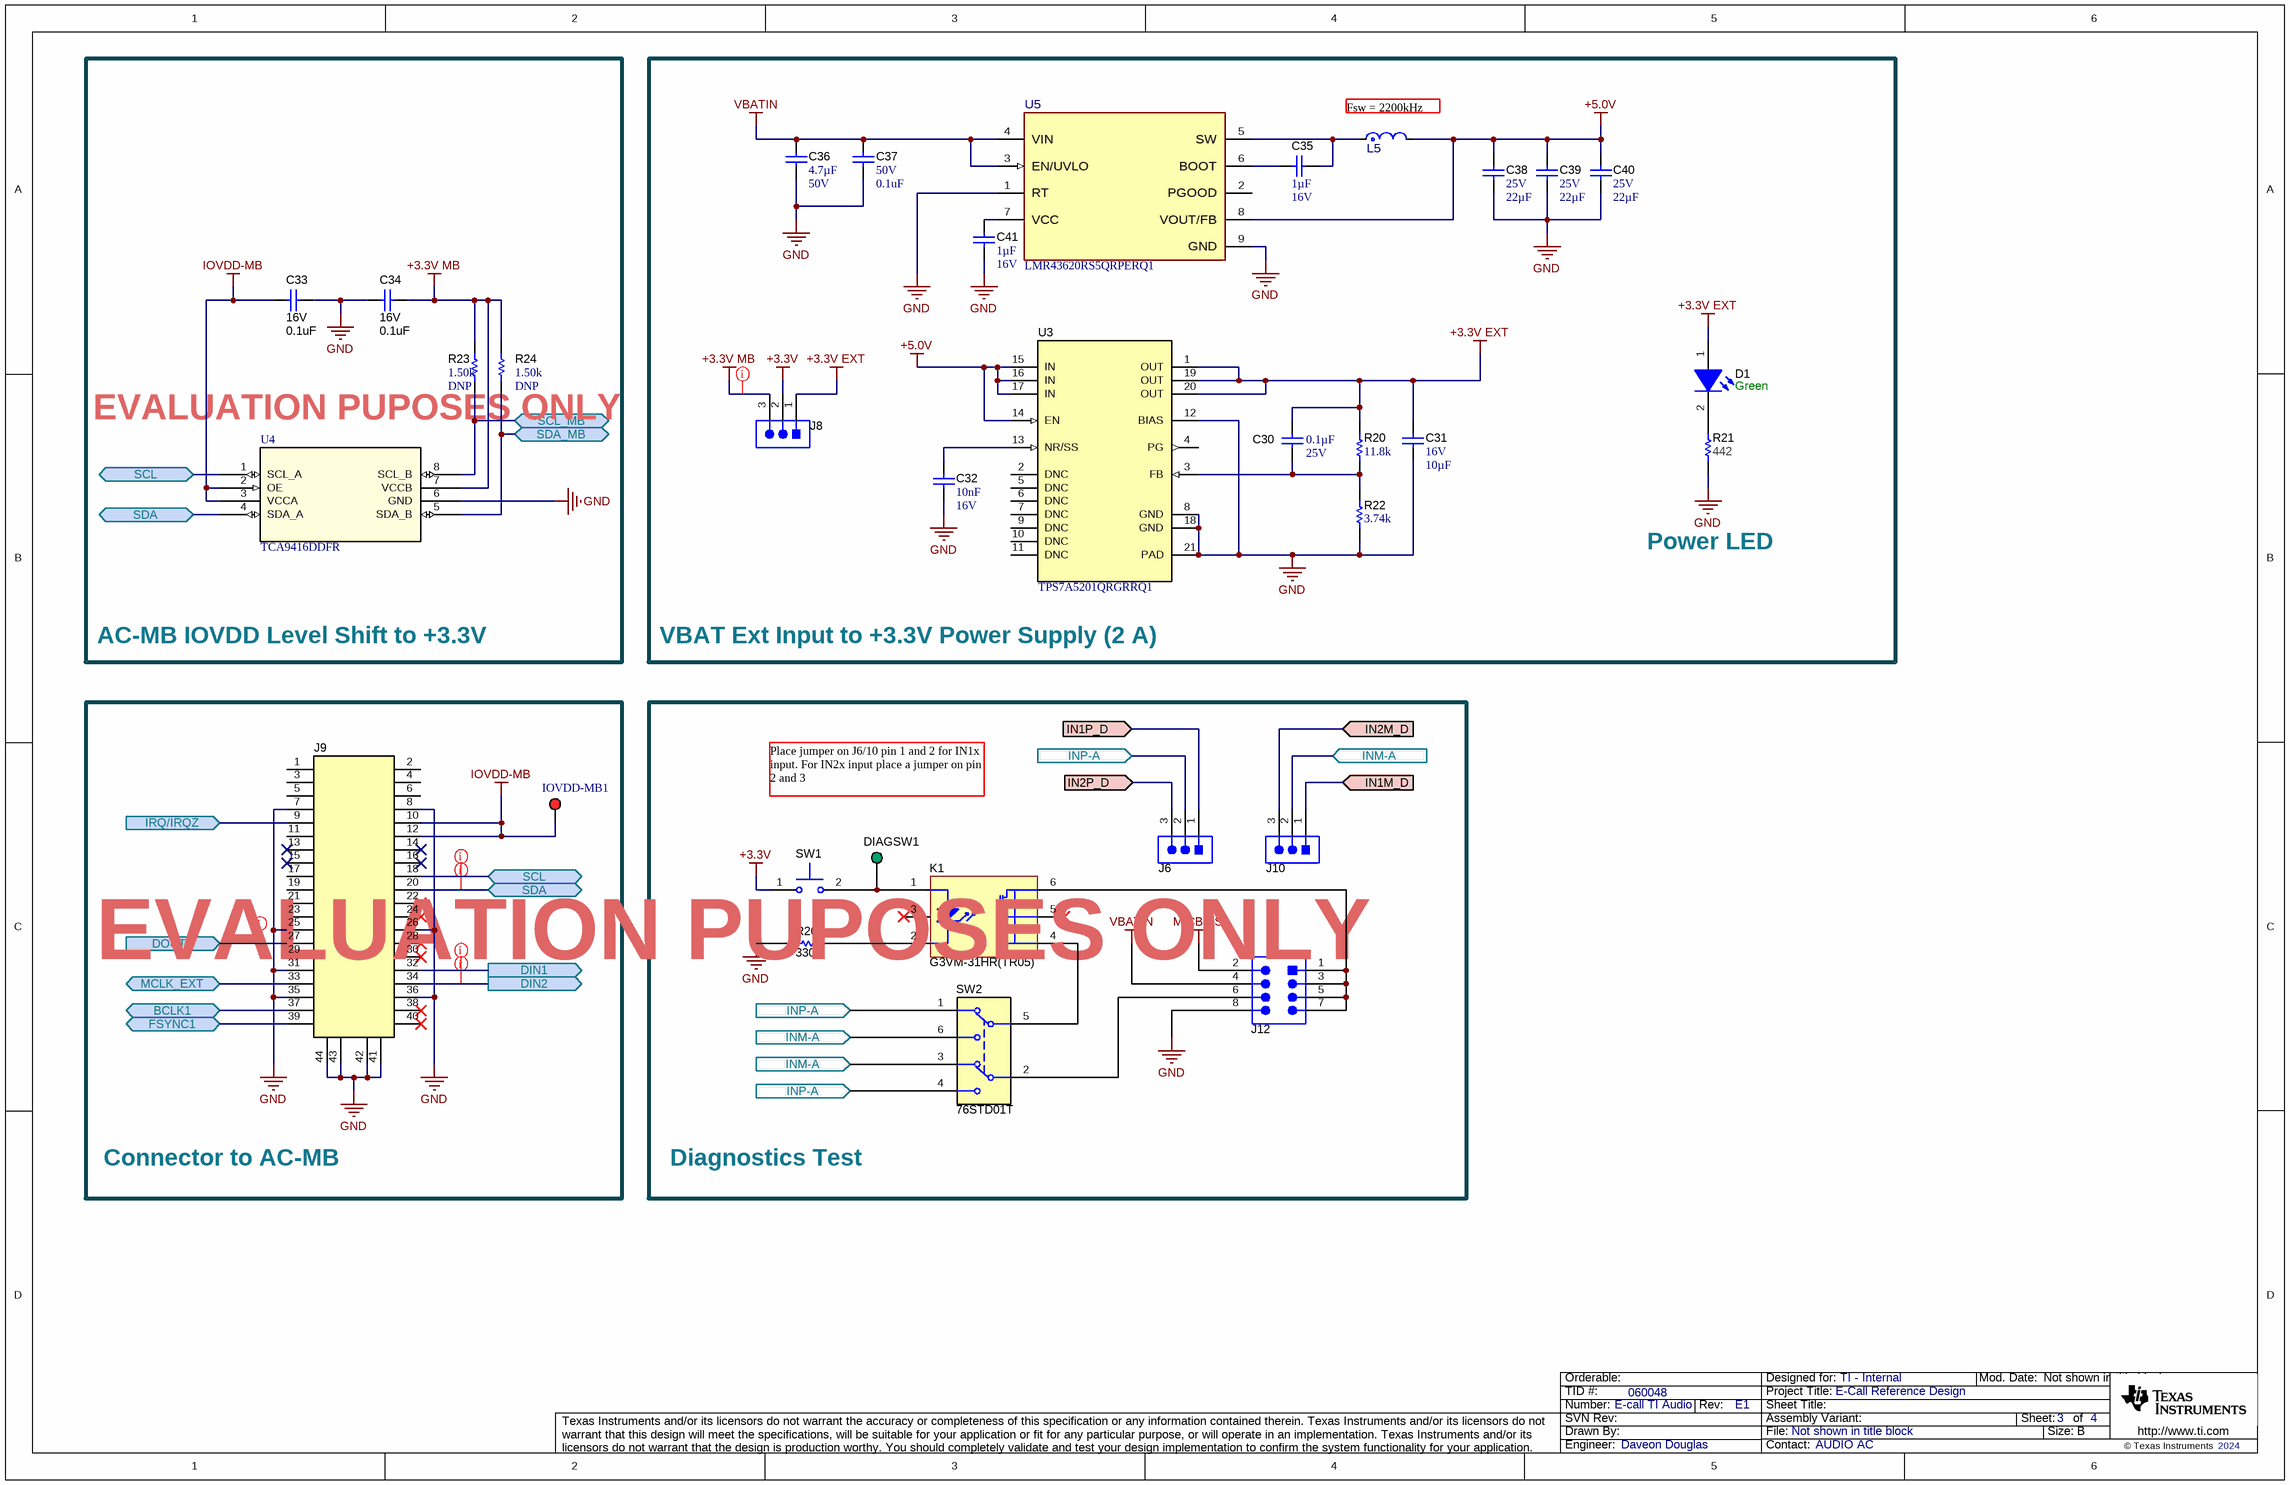
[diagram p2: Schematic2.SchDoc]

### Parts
C30  VDC_V: 25V  ValueDisplayed: 0.1µF  [0402]  (hidden comment: CGA2B3X7R1E104K050BB)
C31  VDC_V: 16V  ValueDisplayed: 10µF  [0805_HV]  (hidden comment: CL21B106KOQNNNG)
C32  Cap_F: 10nF  VDC_V: 16V  [0402_065]  (hidden comment: 520L103KT16T)
C33  VDC_V: 16V  ValueDisplayed: 0.1uF  [0402]  (hidden comment: 885012205037)
C34  VDC_V: 16V  ValueDisplayed: 0.1uF  [0402]  (hidden comment: 885012205037)
C35  Cap_F: 1µF  VDC_V: 16V  [0603]  (hidden comment: GCM188R71C105KA64J)
C36  ValueDisplayed: 4.7µF  VDC_V: 50V  [1210_270]  (hidden comment: GCM32ER71H475KA55L)
C37  VDC_V: 50V  ValueDisplayed: 0.1uF  [0402]  (hidden comment: GCM155R71H104KE02D)
C38  VDC_V: 25V  ValueDisplayed: 22µF  [1210_270]  (hidden comment: TMK325B7226KMHP)
C39  VDC_V: 25V  ValueDisplayed: 22µF  [1210_270]  (hidden comment: TMK325B7226KMHP)
C40  VDC_V: 25V  ValueDisplayed: 22µF  [1210_270]  (hidden comment: TMK325B7226KMHP)
C41  Cap_F: 1µF  VDC_V: 16V  [0603]  (hidden comment: GCM188R71C105KA64J)
D1  value Green  [LTST-C170KGKT_Green]  (hidden comment: LTST-C170KGKT)
DIAGSW1  SHORT A  [Keystone_5116]  (value not drawn)
IOVDD-MB1  5000  [Keystone5000]  (value not drawn)
J6  PBC03SAAN  [PBC03SAAN]  (value not drawn)
J8  TSW-103-07-G-S  [TSW-103-07-G-S]  (value not drawn)
J9  QTE-020-01-L-D-A  [QTE-020-01-X-D-A]  (value not drawn)
J10  PBC03SAAN  [PBC03SAAN]  (value not drawn)
J12  TSW-104-07-G-D  [TSW-104-07-G-D]  (value not drawn)
K1  G3VM-31HR(TR05)  [Omron_SOP-6]
L5  1255AY-3R9N=P3  [FP-1255AY-3R9N=P3_2424 (6060)-MFG]  (value not drawn)
R20  ValueDisplayed: 11.8k  [1206]  (hidden comment: CRCW120611K8FKEA)
R21  ValueDisplayed: 442  [0603L]  (hidden comment: CRCW0603442RFKEA)
R22  ValueDisplayed: 3.74k  [1206]  (hidden comment: CRCW12063K74FKEA)
R23  ValueDisplayed: 1.50k  [0402]  (hidden comment: RMCF0402FT1K50)
R24  ValueDisplayed: 1.50k  [0402]  (hidden comment: RMCF0402FT1K50)
R26  ValueDisplayed: 330  [0402L]  (hidden comment: CRCW0402330RJNED)
SW1  TEST A  [SW_TL1015AF160QG]  (value not drawn)
SW2  76STD01T  [SW_76STD01T]
U3  TPS7A5201QRGRRQ1  [RGR0020A]
U4  TCA9416DDFR  [SOT_16DDFR_TEX]
U5  LMR43620RS5QRPERQ1  [RPE0009A-MFG]

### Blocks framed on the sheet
AC-MB IOVDD Level Shift to +3.3V: C33 C34 R23 R24 U4
Connector to AC-MB: IOVDD-MB1 J9
EVALUATION PUPOSES ONLY: DIAGSW1 J6 J10 J12 K1 R26 SW1 SW2

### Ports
BCLK1 (bidir), DIN1 (out), DIN2 (out), DOUT1 (in), FSYNC1 (bidir), IN1M_D (in), IN1P_D (in), IN2M_D (in), IN2P_D (in), INM-A (in), INP-A (in), IRQ/IRQZ (in), MCLK_EXT (bidir), SCL (bidir), SCL_MB (bidir), SDA (bidir), SDA_MB (bidir)

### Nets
+3.3V: J8.2 SW1.1
+3.3V EXT: C30.1 C31.1 D1.1(A) J8.1 R20.2 U3.1(OUT) U3.19(OUT) U3.20(OUT)
+3.3V MB: C34.2 J8.3 R23.2 R24.2 U4.7(VCCB)
+5.0V: C38.1 C39.1 C40.1 L5.2 U3.14(EN) U3.15(IN) U3.16(IN) U3.17(IN) U5.8(VOUT/FB)
GND: C31.2 C32.2 C33.1 C34.1 C36.2 C37.2 C38.2 C39.2 C40.2 C41.2 J9.7 J9.8 J9.25 J9.26 J9.31 J9.35 J9.36 J9.41 J9.42 J9.43 J9.44 J12.8 R21.2 R22.1 R26.1 U3.8(GND) U3.12(BIAS) U3.18(GND) U3.21(PAD) U4.6(GND) U5.1(RT) U5.9(GND)
IOVDD-MB: C33.2 IOVDD-MB1.1 J9.10 J9.12 U4.2(OE) U4.3(VCCA)
MICBIAS: J12.2
VBATIN: C36.1 C37.1 J12.4 U5.3(EN/UVLO) U5.4(VIN)
BCLK1: J9.37 ; port BCLK1
DIN1: J9.32 ; port DIN1
DIN2: J9.34 ; port DIN2
DOUT1: J9.27 ; port DOUT1
FSYNC1: J9.39 ; port FSYNC1
IN1M_D: J10.1 ; port IN1M_D
IN1P_D: J6.1 ; port IN1P_D
IN2M_D: J10.3 ; port IN2M_D
IN2P_D: J6.3 ; port IN2P_D
INM-A: J10.2 SW2.3(NO) SW2.6(NC) ; port INM-A
INP-A: J6.2 SW2.1(NO) SW2.4(NC) ; port INP-A
IRQ/IRQZ: J9.9 J9.33 ; port MCLK_EXT, port IRQ/IRQZ
SCL: J9.18 R23.1 U4.1(SCL_A) U4.8(SCL_B) ; port SCL, port SCL_MB
SDA: J9.20 R24.1 U4.4(SDA_A) U4.5(SDA_B) ; port SDA, port SDA_MB
NetC30_2: C30.2 R20.1 R22.2 U3.3(FB)
NetC32_1: C32.1 U3.13(NR/SS)
NetC35_1: C35.1 U5.6(BOOT)
NetC35_2: C35.2 L5.1 U5.5(SW)
NetC41_1: C41.1 U5.7(VCC)
NetD1_2: D1.2(K) R21.1
NetDIAGSW1_1: DIAGSW1.1 K1.1 SW1.2
NetJ12_1: J12.1 J12.3 J12.5 J12.7 K1.6
NetJ12_6: J12.6 SW2.2(COM)
NetK1_2: K1.2 R26.2
NetK1_4: K1.4 SW2.5(COM)

Not connected (* = marked no-connect by the designer): J9 1 2 3 4 5 6 11 13* 14* 15* 16* 17 19 21 22* 23 24* 28* 29 30* 38* 40*; K1 3* 5*; U3 2(DNC) 4(PG) 5(DNC) 6(DNC) 7(DNC) 9(DNC) 10(DNC) 11(DNC); U5 2(PGOOD)

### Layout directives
net class ASI: DIN1, DIN2, DOUT1
net class I2C: SCL, SDA
net class PWR: +3.3V MB

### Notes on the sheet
- (near L5) Fsw = 2200kHz
- (near R23) DNP
- (near R24) DNP
- EVALUATION PUPOSES ONLY
- Power LED
- VBAT Ext Input to +3.3V Power Supply (2 A)
- Place jumper on J6/10 pin 1 and 2 for IN1x input. For IN2x input place a jumper on pin 2 and 3
- Diagnostics Test

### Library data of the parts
C30 = CMP-0080610-1: CAP, CERM, 0.1 µF, 25 V,+/- 10%, X7R, AEC-Q200 Grade 1, 0402; Manufacturer: TDK; Value: 0.1uF; TaMin_C: -55°C; Polarized: N; SizeAreaWB_mm2: 3; U/M: EA; TaMax_C: 125°C; SizeZ_mm: 0.6; SizeX_mm: 1; SizeY_mm: 0.5; AEC Qualified: Y; Cap_F: 100nF; AEC Category: Q200
C31 = CMP-0860967-1: CAP, CERM, 10 µF, 16 V,+/- 10%, X7R, 0805; Manufacturer: Samsung; SizeZ_mm: 1.45; AEC Category: Q200; AEC Qualified: N; TaMin_C: -55°C; Cap_Case: 0805; SizeY_mm: 1.25; SizeAreaWB_mm2: 6.75; SizeArea_mm2: 2.5; TaMax_C: 125°C; SizeX_mm: 2; Value: 10uF; U/M: EA
C32 = CMP-0006210-2: CAP, CERM, 0.01 uF, 16 V, +/- 10%, X7R, 0402; Manufacturer: AT Ceramics; TaMin_C: -55°C; Polarized: N; SizeAreaWB_mm2: 3; Value1: Unknown; U/M: EA; Value: 0.01uF; TaMax_C: 125°C; SizeZ_mm: 0.65; SizeX_mm: 1; SizeY_mm: 0.5; Cap_Case: 0402; AEC Category: Q200
C33 C34 = CMP-0006228-2: as C14 on sheet Schematic1
C35 C41 = CMP-0079154-1: CAP, CERM, 1 µF, 16 V,+/- 10%, X7R, AEC-Q200 Grade 1, 0603; Manufacturer: MuRata; SizeAreaWB_mm2: 4.68; SizeArea_mm2: 1.28; AEC Qualified: Y; AEC Category: Q200; Value: 1uF; TaMax_C: 125°C; SizeZ_mm: 1; Polarized: N; TaMin_C: -55°C; SizeY_mm: 0.8; U/M: EA; SizeX_mm: 1.6
C36 = CMP-0750153-1: CAP, CERM, 4.7 µF, 50 V,+/- 10%, X7R, AEC-Q200 Grade 1, 1210; Manufacturer: MuRata; Polarized: N; TaMin_C: -55°C; TaMax_C: 125°C; SizeAreaWB_mm2: 14.7; SizeY_mm: 2.5; AEC Category: Q200; Value: 4.7uF; Cap_Case: 1210; AEC Qualified: Y; AEC Grade: 1; SizeArea_mm2: 8; SizeZ_mm: 2.7; U/M: EA; SizeX_mm: 3.2
C37 = CMP-0006356-2: CAP, CERM, 0.1 uF, 50 V, +/- 10%, X7R, AEC-Q200 Grade 1, 0402; Manufacturer: MuRata; TaMin_C: -55°C; Polarized: N; SizeAreaWB_mm2: 3; Value1: Unknown; U/M: EA; Value: 0.1uF; TaMax_C: 125°C; SizeZ_mm: 0.6; SizeX_mm: 1; SizeY_mm: 0.5; AEC Qualified: Y; Cap_F: 100nF; AEC Category: Q200
C38-C40 = CMP-0080552-1: CAP, CERM, 22 µF, 25 V,+/- 10%, X7R, AEC-Q200 Grade 1, 1210; Manufacturer: Taiyo Yuden; TaMin_C: -55°C; Polarized: N; SizeAreaWB_mm2: 14.7; U/M: EA; Value: 22uF; TaMax_C: 125°C; SizeZ_mm: 2.7; SizeX_mm: 3.2; SizeY_mm: 2.5; Cap_Case: 1210; SizeArea_mm2: 8; AEC Qualified: Y; AEC Category: Q200; AEC Grade: 1
D1 = CMP-0002888-2: LED, Green, SMD; Manufacturer: Lite-On; Type: AlInGaP; Vf_V: 2V; Io_A: 20mA; Value1: W
DIAGSW1 = CMP-0055164-1: as MICBIAS1 on sheet Schematic1
IOVDD-MB1 = CMP-0055137-2: as AVDD on sheet Schematic1
J6 J10 = CMP-0002334-1: Header, 100mil, 3x1, Gold, TH; Manufacturer: Sullins Connector Solutions; CNHeader: TRUE; Green_Lifecycle: Not Set; Green_REACh: Incomplete; CT: FALSE
J8 = CMP-0075407-2: Header, 100mil, 3x1, Gold, TH; Manufacturer: Samtec; Pitch_mm: 2.54; Cert_VDE: N; Gender: Male; Cert_CSA: Y; Voltage_V: 550V; Green_REACh: Passed; Current_A: 6.3A; Green_Lifecycle: Active; Row_Count: 1
J9 = CMP-0055951-1: Connector, Header, High Speed, 20 pairs, SMT; Manufacturer: Samtec; CT: FALSE; Green_REACh: Passed; Green_Lifecycle: Active
J12 = CMP-0075408-3: Header, 100mil, 4x2, Gold, TH; Manufacturer: Samtec; Pitch_mm: 2.54; Cert_VDE: N; Gender: Male; Cert_CSA: Y; Voltage_V: 550V; Green_REACh: Passed; Current_A: 6.3A; Green_Lifecycle: Active; Row_Count: 2
K1 = CMP-0082600-1: Relay, SPST-NO (1 Form A), 4 A, SMD; Manufacturer: Omron Electronic Components; Contact Rating_A: 4A
L5 = CMP-0121228-1: Shielded Wirewound Inductor 3.9uH 30% 4200mA 0.0264Ω SMD; Manufacturer: Murata; AEC Qualified: No; DCR_ohm: 26.4m; Ind_H: 3.9µH; Isat: 4700mA; Material: Ferrite; SizeZ_mm: 4.5mm; Shrouded: true; Test Frequency: 100kHz; Tolerance_%: 0.3%
R20 = CMP-0016598-3: RES, 11.8 k, 1%, 0.25 W, AEC-Q200 Grade 0, 1206; Manufacturer: Vishay-Dale; Power_W: 250mW; TempCo: 100 ppm/C; Value_Code: 11k8; Value: 11.8k; EIA_Code: E96; SizeX_mm: 3.2; SizeY_mm: 1.6; SizeZ_mm: 1.35; Value2: 0.25W; SizeArea_mm2: 5.12; AEC Qualified: Y; VDC_V: 200V; AEC Category: Q200; AEC Grade: 0
R21 = CMP-0022425-5: RES, 442, 1%, 0.1 W, AEC-Q200 Grade 0, 0603; Manufacturer: Vishay-Dale; Value: 442; Value_Code: 442R; Power_W: 100mW; Value2: 0.1W; VDC_V: 75V; TempCo: 100 ppm/C; EIA_Code: E96; AEC Category: Q200; AEC Qualified: Y; AEC Grade: 0; SizeArea_mm2: 1.28; SizeX_mm: 1.6; SizeY_mm: 0.8; SizeZ_mm: 1
R22 = CMP-0016952-3: RES, 3.74 k, 1%, 0.25 W, AEC-Q200 Grade 0, 1206; Manufacturer: Vishay-Dale; Power_W: 250mW; TempCo: 100 ppm/C; Value_Code: 3k74; Value: 3.74k; EIA_Code: E96; SizeX_mm: 3.2; SizeY_mm: 1.6; SizeZ_mm: 1.35; Value2: 0.25W; SizeArea_mm2: 5.12; AEC Qualified: Y; VDC_V: 200V; AEC Category: Q200; AEC Grade: 0
R23 R24 = CMP-0026756-1: RES, 1.50 k, 1%, 0.063 W, AEC-Q200 Grade 0, 0402; Manufacturer: Stackpole Electronics Inc; Power_W: 63mW; TempCo: 100 ppm/C; Value_Code: 1k50; U/M: EA; Value: 1.50k; EIA_Code: E96; Res_ohm: 1.5k; SizeX_mm: 1; SizeY_mm: 0.5; SizeZ_mm: 0.6; Value2: 0.063W; AEC Qualified: Y; VDC_V: 50V; AEC Grade: 0; AEC Category: Q200
R26 = CMP-0026906-3: RES, 330, 5%, 0.063 W, AEC-Q200 Grade 0, 0402; Manufacturer: Vishay-Dale; Power_W: 63mW; TempCo: 200 ppm/C; Value_Code: 330R; Value: 330; EIA_Code: E24; SizeX_mm: 1; SizeY_mm: 0.5; SizeZ_mm: 0.6; Value2: 0.063W; CompType: Resistor; AEC Qualified: Y; VDC_V: 50V; AEC Category: Q200; AEC Grade: 0
SW1 = CMP-0002143-3: Switch, Tactile, SPST-NO, 0.05A, 12V, SMT; PartNumber: TL1015AF160QG; Manufacturer: E-Switch; CurrentRating_mA: 50A; PositionCount: 1; SwitchFunction: Off-Mom
SW2 = CMP-0082634-2: Switch, DPDT, 0.15 A, 30 VDC, TH; Manufacturer: Grayhill; SizeAreaWB_mm2: 135.7225; SizeArea_mm2: 93.1225; SizeZ_mm: 12.37; SizeY_mm: 9.65; VDC_V: 30V; CurrentRating_mA: 150A; PositionCount: 2
U3 = CMP-0077252-2: Automotive-Grade 2-A, High-Accuracy, Low-Noise, LDO Voltage Regulator, RGR0020A (VQFN-20); Alternate Manufacturer: Texas Instruments; AEC Qualified: Y; CompType: IC; SizeX_mm: 3.5; SizeAreaWB_mm2: 20.25; AEC Category: Q200; SizeZ_mm: 1.0; SizeArea_mm2: 12.25
U4 = TCA9416DDFR: No Description Available; Mfr_Name: Texas Instruments
U5 = CMP-0095155-1: 36-V, 1-A/2-A Buck Converter with <3 µA IQ at 150°C TJMAX in 4-mm2 HotRod™ QFN; Manufacturer: Texas Instruments; Max Supply Voltage: 36V; Output Type: Fixed,AdjustableProgrammable; Switching Frequency: 200-2200kHz; TaMax_C: +125°C; Min Supply Voltage: 3V; Standoff Height: 0mm; TJmax_C: +150°C; AEC Qualified: Yes; AEC Grade: Grade 1; Number Of Outputs: 1; Nominal Supply Current: 1.2uA; Max Duty Cycle: 98%; SizeZ_mm: 1mm; Output Voltage: 5/1-34.2V; TaMin_C: -40°C

## Sheet Hardware.SchDoc
size 431 x 279 mm; Date: Not shown in title block; ApprovedBy: Not shown in title block; CheckedBy: Not shown in title block; Author: Not shown in title block; CompanyName: Not shown in title block; Engineer: Not shown in title block; Organization: Not shown in title block; Address1: Not shown in title block; Address2: Not shown in title block; Address3: Not shown in title block; Address4: Not shown in title block; DocumentNumber: 3; Revision: Use project parameter SCH_Rev; SheetNumber: 4; SheetTotal: 4; PageSetup: Record=PageOptions¦CenterHorizontal=True¦CenterVertical=True¦PrintScale=1.00¦XCorrection=1.00¦YCorrection=1.00¦PrintKind=0¦BorderSize=5000000¦LeftOffset=0¦BottomOffset=0¦Orientation=2¦PaperLength=1000¦PaperWidth=1000¦Scale=100¦PaperSource=15¦PrintQuality=600¦MediaType=1¦DitherType=10¦PaperKind=Letter¦PrintScaleMode=1
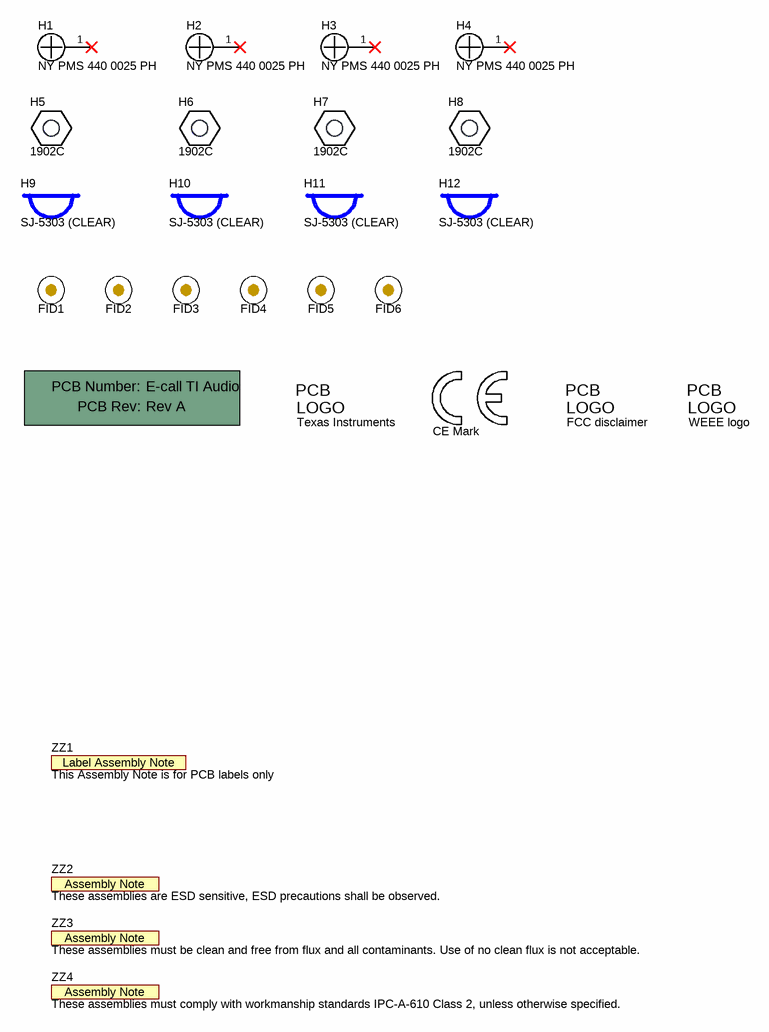
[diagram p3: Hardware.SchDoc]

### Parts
!PCB  Printed Circuit Board  (value not drawn)  (mechanical)
FID1  Fiducial  [Fiducial10-20]  (value not drawn)
FID2  Fiducial  [Fiducial10-20]  (value not drawn)
FID3  Fiducial  [Fiducial10-20]  (value not drawn)
FID4  Fiducial  [Fiducial10-20]  (value not drawn)
FID5  Fiducial  [Fiducial10-20]  (value not drawn)
FID6  Fiducial  [Fiducial10-20]  (value not drawn)
H1  NY PMS 440 0025 PH  [NY PMS 440 0025 PH]
H2  NY PMS 440 0025 PH  [NY PMS 440 0025 PH]
H3  NY PMS 440 0025 PH  [NY PMS 440 0025 PH]
H4  NY PMS 440 0025 PH  [NY PMS 440 0025 PH]
H5  1902C  [Keystone_1902C]
H6  1902C  [Keystone_1902C]
H7  1902C  [Keystone_1902C]
H8  1902C  [Keystone_1902C]
H9  SJ-5303 (CLEAR)  [Bumpon_SJ5003Transparent]
H10  SJ-5303 (CLEAR)  [Bumpon_SJ5003Transparent]
H11  SJ-5303 (CLEAR)  [Bumpon_SJ5003Transparent]
H12  SJ-5303 (CLEAR)  [Bumpon_SJ5003Transparent]
Logo1  Texas Instruments  [TI_Stacked_Overlay_Small]  (no BOM)
Logo2  CE Mark  [CE_Mark_5mm]  (no BOM)
Logo3  FCC disclaimer  [FCC_disclaimer]  (no BOM)
Logo4  WEEE logo  [WEEE_Minimum]  (no BOM)
ZZ1  This Assembly Note is for PCB labels only  [AssemblyNoteLabel]  (no BOM)
ZZ2  These assemblies are ESD sensitive, ESD precautions shall be observed.  [AssemblyNote]  (no BOM)
ZZ3  These assemblies must be clean and free from flux and all contaminants. Use of no clean flux is not acceptable.  [AssemblyNote]  (no BOM)
ZZ4  These assemblies must comply with workmanship standards IPC-A-610 Class 2, unless otherwise specified.  [AssemblyNote]  (no BOM)

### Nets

Not connected (* = marked no-connect by the designer): H1 1*; H2 1*; H3 1*; H4 1*

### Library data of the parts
!PCB = CMP-0003618-2: Manufacturer: Any; PartNumber: E-call TI Audio
FID1-FID6 = CMP-0077181-1: Fiducial mark.  There is nothing to buy or mount.
H1-H4 = CMP-0003617-1: Machine Screw, Round, #4-40 x 1/4, Nylon, Philips panhead; Manufacturer: B&F Fastener Supply; CompType: Hardware
H5-H8 = CMP-0003610-1: Standoff, Hex, 0.5"L #4-40 Nylon; Manufacturer: Keystone; CompType: Hardware
H9-H12 = CMP-0003620-1: Bumpon, Hemisphere, 0.44 X 0.20, Clear; Manufacturer: 3M
Logo1 = CMP-0074838-1: Texas Instrument Corporate Signature; SymbolCreator: a0412235; Lib Reference: TI_Logo; Library Reference: Logo
Logo2 = CMP-0074844-1: SymbolCreator: a0412235
Logo3 = CMP-0074847-1: FCC_disclaimer; Library Reference: Logo
Logo4 = CMP-0074769-3: Manufacturer: Texas Instruments; AEC Category: Q200; CompType: IC
ZZ1 = CMP-0003616-3
ZZ2 = CMP-0077236-1
ZZ3 = CMP-0077237-1
ZZ4 = CMP-0077238-1

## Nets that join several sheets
+3.3V: Schematic1 (13 pins), Schematic2 (J8.2 SW1.1)
GND: Schematic1 (44 pins), Schematic2 (32 pins)
MICBIAS: Schematic1 (6 pins), Schematic2 (J12.2)
VBATIN: Schematic1 (8 pins), Schematic2 (5 pins)
BCLK1: Schematic1 (BCLK1.1 J4.3 R8.2), Schematic2 (J9.37)
DIN1: Schematic1 (DIN1.1 J4.5 R9.2), Schematic2 (J9.32)
DOUT1: Schematic1 (DOUT1.1 J4.7 R10.2), Schematic2 (J9.27)
FSYNC1: Schematic1 (FSYNC1.1 J4.9 R11.2), Schematic2 (J9.39)
IN1M_D: Schematic1 (5 pins), Schematic2 (J10.1)
IN1P_D: Schematic1 (5 pins), Schematic2 (J6.1)
IN2M_D: Schematic1 (MIC2M.1 MK2.2 R17.1 U2.18), Schematic2 (J10.3)
IN2P_D: Schematic1 (MIC2P.1 MK2.1 R14.2 U2.17), Schematic2 (J6.3)
IRQ/IRQZ: Schematic1 (J4.1 MCLK.1 U2.9), Schematic2 (J9.9 J9.33)
SCL: Schematic1 (5 pins), Schematic2 (J9.18 R23.1 U4.1 U4.8)
SDA: Schematic1 (5 pins), Schematic2 (J9.20 R24.1 U4.4 U4.5)

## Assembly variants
001: not fitted C5 C11 FID1 FID2 FID3 FID4 FID5 FID6 R1 R4 R23 R24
